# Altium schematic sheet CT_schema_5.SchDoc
size 293 x 258 mm
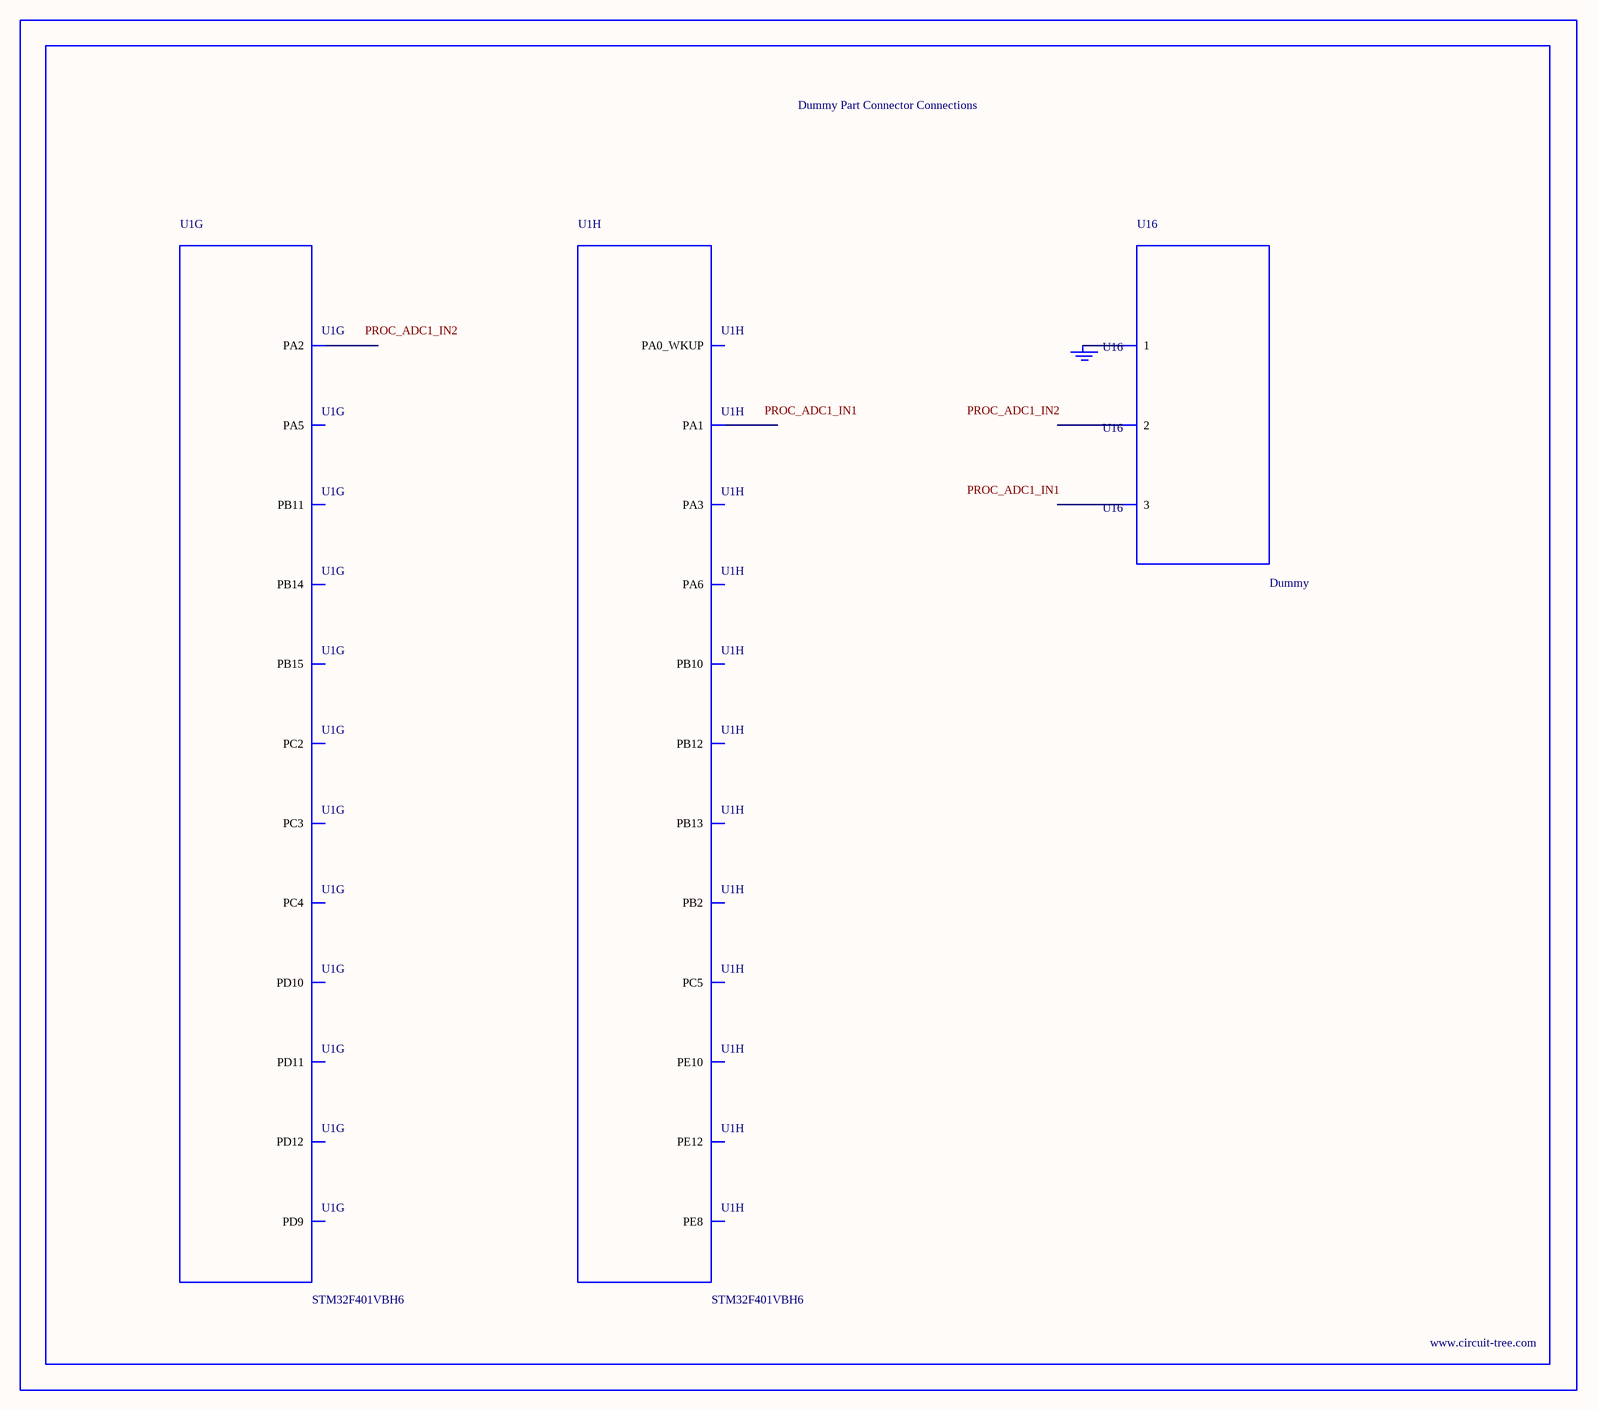
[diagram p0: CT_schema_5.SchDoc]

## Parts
BORDER4  (no value)
GND_INSTANCE_4_0  (no value)
U1  STM32F401VBH6  [UFBGA100]  (parts G,H of 8)
U16  Dummy  [DUMMY_PACKAGE_207]

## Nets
NetGND_INSTANCE_4_0_0: GND_INSTANCE_4_0.0(GND) U16.1

Not connected (* = marked no-connect by the designer): U1 J3(PC2) J10(PD12) J11(PD11) J12(PD10) K2(PC3) K3(PA2) K4(PA5) K5(PC4) K8(PD9) K9(PB11) K10(PB15) K11(PB14) K12(PB13) L2(PA0_WKUP) L3(PA3) L4(PA6) L5(PC5) L6(PB2) L7(PE8) L8(PE10) L9(PE12) L10(PB10) L12(PB12) M2(PA1); U16 2 3

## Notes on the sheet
- Labels drawn without touching a wire or pin: PROC_ADC1_IN1, PROC_ADC1_IN2

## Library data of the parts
BORDER4 = BORDER_PAGE4
GND_INSTANCE_4_0 = GND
